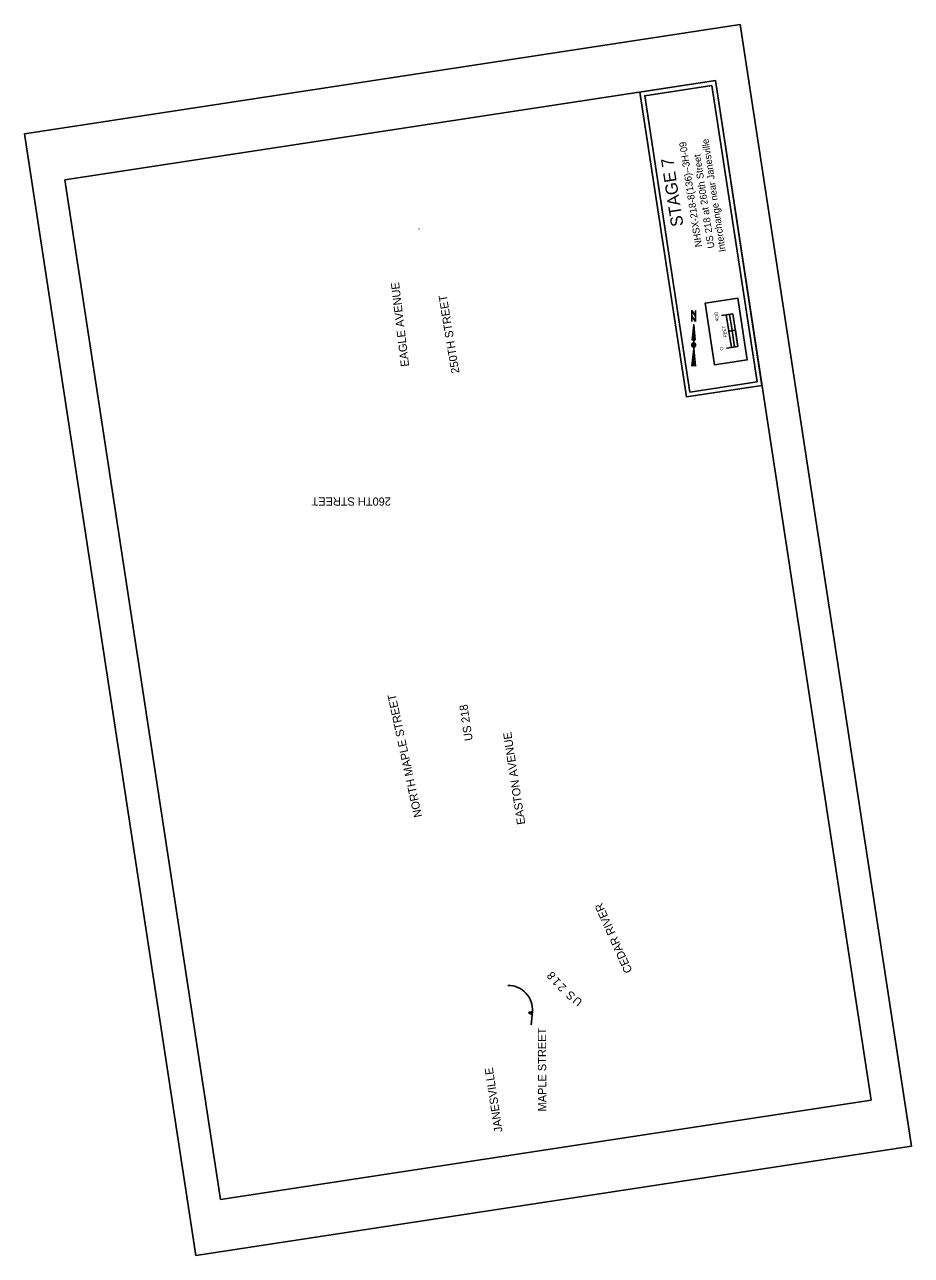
# Model space of a CAD drawing. Extents: x 5192026 to 5202808, y 3700291 to 3715256.
import ezdxf

# ---------------------------------------------------------------- set-up
doc = ezdxf.new("R2010")
doc.units = 0
for name, color, linetype in [('dsnCellElements', 7, 'Continuous'), ('dsnPavementRemovalHatch', 7, 'Continuous'), ('dsnTextFinalPlan', 7, 'Continuous'), ('Level 1', 7, 'Continuous'), ('Level 2', 7, 'Continuous'), ('Level 5', 7, 'Continuous'), ('phoSurveyDescript', 7, 'Continuous'), ('phoSurveyPointsNonDTM', 7, 'Continuous')]:
    doc.layers.add(name, color=color, linetype=linetype)

msp = doc.modelspace()

# ---------------------------------------------------------------- linework, layer by layer
at = {"layer": 'dsnCellElements'}
for p, q in [((5198158, 3703248), (5198186, 3703250)), ((5198158, 3703248), (5198186, 3703250)), ((5198159, 3703231), (5198158, 3703248)), ((5198159, 3703231), (5198158, 3703248)), ((5198186, 3703094), (5198200, 3703254)), ((5198186, 3703094), (5198200, 3703254)), ((5198197, 3703220), (5198200, 3703257)), ((5198200, 3703257), (5198197, 3703220)), ((5198182, 3703229), (5198159, 3703231))]:
    msp.add_line(p, q, dxfattribs=at)
for centre, radius, start, end in [((5197906, 3703279), 295, 355.0831, 90.5978), ((5198185, 3703270), 20, 272.8175, 358.0701), ((5198185, 3703270), 20, 272.8175, 358.0701), ((5198180, 3703209), 20, 355.0839, 84.4202)]:
    msp.add_arc(centre, radius, start, end, dxfattribs=at)
at = {"layer": 'dsnPavementRemovalHatch'}
for p, q in [((5200161, 3711607), (5200180, 3711417)), ((5200161, 3711607), (5200161, 3711113)), ((5200142, 3711419), (5200146, 3711423)), ((5200142, 3711417), (5200142, 3711417)), ((5200161, 3711336), (5200161, 3711336)), ((5200137, 3711103), (5200161, 3711312))]:
    msp.add_line(p, q, dxfattribs=at)
msp.add_lwpolyline([(5200185, 3711645), (5200137, 3711712), (5200137, 3711778), (5200185, 3711712)], close=True, dxfattribs=at)
for points in [[(5200137, 3711645), (5200137, 3711778), (5200185, 3711712), (5200185, 3711778)], [(5200142, 3711417), (5200161, 3711607), (5200161, 3711426)], [(5200161, 3711336), (5200161, 3711360), (5200137, 3711360)], [(5200185, 3711360), (5200161, 3711360), (5200161, 3711384)], [(5200161, 3711113), (5200161, 3711312), (5200185, 3711103)]]:
    msp.add_lwpolyline(points, dxfattribs=at)
for centre, radius, start, end in [((5200161, 3711360), 23.8, 90, 180), ((5200161, 3711360), 23.8, 180, 270), ((5200161, 3711403), 23.8, 90.0204, 143.1257), ((5200161, 3711403), 23.8, 36.8481, 90.0218), ((5200161, 3711360), 23.8, 0, 90), ((5200161, 3711360), 23.8, 270, 360), ((5200161, 3711078), 34.4, 89.9894, 133.619), ((5200161, 3711078), 34.5, 46.4021, 90.0006)]:
    msp.add_arc(centre, radius, start, end, dxfattribs=at)
at = {"layer": 'dsnTextFinalPlan'}
for points in [[(5194109, 3700291), (5202808, 3701620), (5200726, 3715256), (5192026, 3713927)], [(5194410, 3700971), (5202318, 3702179), (5200425, 3714575), (5192516, 3713368)]]:
    msp.add_lwpolyline(points, close=True, dxfattribs=at)
at = {"layer": 'Level 1'}
msp.add_line((5200668, 3711541), (5200588, 3711529), dxfattribs=at)
msp.add_line((5200668, 3711541), (5200588, 3711529), dxfattribs=at)
for points in [[(5200416, 3711118), (5200302, 3711869), (5200697, 3711930), (5200812, 3711178)], [(5200812, 3711178), (5200416, 3711118), (5200302, 3711869), (5200697, 3711930)], [(5200628, 3711535), (5200597, 3711732), (5200558, 3711726), (5200588, 3711529)], [(5200698, 3711343), (5200668, 3711541), (5200628, 3711535), (5200658, 3711337)]]:
    msp.add_lwpolyline(points, close=True, dxfattribs=at)
for points in [[(5200559, 3711322), (5200698, 3711343), (5200637, 3711739), (5200499, 3711717)], [(5200619, 3711331), (5200558, 3711726)]]:
    msp.add_lwpolyline(points, dxfattribs=at)
at = {"layer": 'Level 2'}
msp.add_lwpolyline([(5194410, 3700971), (5192516, 3713368), (5200425, 3714575), (5202318, 3702179)], close=True, dxfattribs=at)
at = {"layer": 'Level 5'}
for points in [[(5200072, 3710728), (5199505, 3714435), (5200425, 3714575), (5200991, 3710868)], [(5200116, 3710788), (5199566, 3714391), (5200381, 3714515), (5200931, 3710912)]]:
    msp.add_lwpolyline(points, close=True, dxfattribs=at)
for points in [[(5200991, 3710868), (5200425, 3714575), (5199505, 3714435), (5200072, 3710728), (5200991, 3710868)], [(5200116, 3710788), (5199566, 3714391), (5200381, 3714515), (5200931, 3710912), (5200116, 3710788)]]:
    msp.add_lwpolyline(points, dxfattribs=at)
at = {"layer": 'phoSurveyPointsNonDTM'}
for q in [(5196823, 3712774), (5196823, 3712770)]:
    msp.add_line((5196823, 3712770), q, dxfattribs=at)

# ---------------------------------------------------------------- texts
at = {"layer": 'Level 1'}
for s, height, p in [('NHSX-218-8(136)--3H-09', 85, (5200263, 3712557)), ('Interchange near Janesville', 85, (5200551, 3712498)), ('  US 218 at 260th Street ', 85, (5200425, 3712479)), ('4OO', 40, (5200468, 3711653)), ('FEET', 40, (5200567, 3711457)), ('O', 40, (5200523, 3711296)), ('O', 40, (5200523, 3711296))]:
    msp.add_text(s, height=height, rotation=98.6831, dxfattribs=at).set_placement(p)
at = {"layer": 'Level 2'}
for s, rotation, p in [('EAGLE AVENUE', 96.8932, (5196702, 3711103)), ('250TH STREET', 99.3981, (5197315, 3711022)), ('260TH STREET', 179.8345, (5196480, 3709506)), ('NORTH MAPLE STREET', 102.2339, (5196860, 3705628)), ('US 218', 98.6831, (5197476, 3706555)), ('EASTON AVENUE', 98.6831, (5198114, 3705536)), ('CEDAR RIVER', 114.0562, (5199418, 3703750)), ('8', 129.328, (5198491, 3703695)), ('1', 131.4754, (5198554, 3703624)), ('2', 134.1916, (5198621, 3703555)), ('S', 139.0446, (5198730, 3703458)), ('U', 141.745, (5198817, 3703388)), ('MAPLE STREET', 90.1417, (5198369, 3702041)), ('JANESVILLE', 98.6831, (5197838, 3701796))]:
    msp.add_text(s, height=100, rotation=rotation, dxfattribs=at).set_placement(p)
at = {"layer": 'phoSurveyDescript'}
msp.add_text('STAGE 7', height=148.9, rotation=98.6831, dxfattribs=at).set_placement((5200037, 3712812))

doc.saveas('drawing.dxf')
